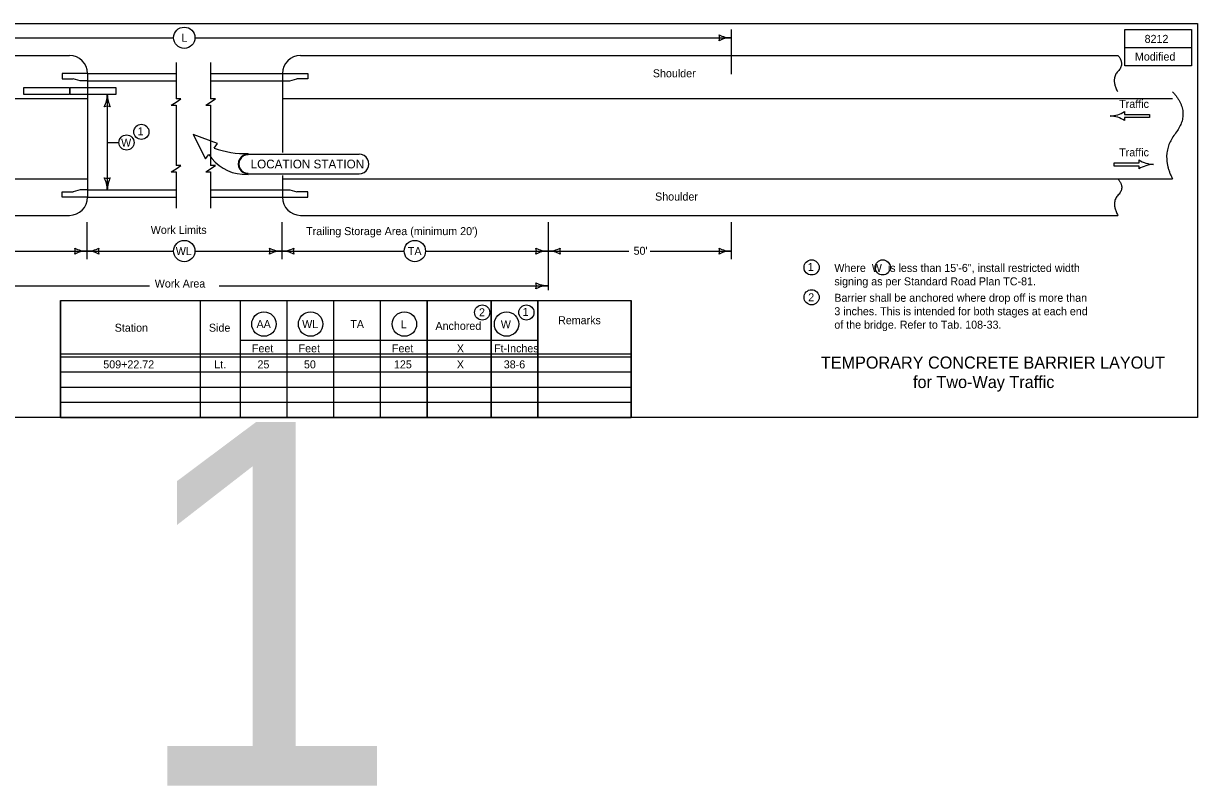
# Model space of a CAD drawing. Extents: x 6410 to 81668, y 3928 to 11667.
# Drawn here: x 11320 to 13257, y 10409 to 11667 of the extents above; entities that cross this region are included whole.
import ezdxf

# ---------------------------------------------------------------- set-up
doc = ezdxf.new("R2010")
doc.units = 0
doc.layers.add('dsnStdSection', color=7, linetype='Continuous')

msp = doc.modelspace()

# ---------------------------------------------------------------- linework, layer by layer
at = {"layer": 'dsnStdSection'}
for p, q in [((10152.2, 11666.6), (13257.2, 11666.6)), ((13257.2, 11666.6), (13257.2, 11016.6)), ((10635.1, 11643), (11568, 11643)), ((11603, 11643), (12487.8, 11643)), ((11615.6, 11643), (11746.2, 11643)), ((12487.8, 11656.8), (12487.8, 11583.2)), ((10267.5, 11614), (11396, 11614)), ((11777.4, 11614), (13125.8, 11614)), ((11426, 11584), (11384, 11584)), ((11384, 11584), (11384, 11575)), ((11426, 11584), (11572, 11584)), ((11426, 11584), (11426, 11380)), ((11572, 11602), (11572, 11542.1)), ((11629, 11602), (11629, 11542.1)), ((11629, 11584), (11747.4, 11584)), ((11747.4, 11584), (11789.4, 11584)), ((11747.4, 11584), (11747.4, 11453.9)), ((11789.4, 11584), (11789.4, 11575)), ((11384, 11575), (11402, 11575)), ((11414, 11572), (11402, 11575)), ((11426, 11572), (11414, 11572)), ((11426, 11572), (11572, 11572)), ((11629, 11572), (11747.4, 11572)), ((11747.4, 11572), (11759.4, 11572)), ((11759.4, 11572), (11771.4, 11575)), ((11789.4, 11575), (11771.4, 11575)), ((11458.5, 11549.2), (11458.5, 11392)), ((10179.2, 11542.9), (11426, 11542.9)), ((11564, 11532), (11572, 11537)), ((11564, 11532), (11572, 11532)), ((11572, 11537), (11580, 11542.1)), ((11580, 11542.1), (11572, 11542.1)), ((11572, 11532), (11572, 11482)), ((11621, 11532), (11637, 11542.1)), ((11621, 11532), (11629, 11532)), ((11637, 11542.1), (11629, 11542.1)), ((11629, 11532), (11629, 11482)), ((11747.4, 11542.9), (13216.1, 11542.9)), ((13113, 11513.9), (13113, 11513.9)), ((13136.9, 11521.4), (13136.9, 11516.2)), ((13136.9, 11516.2), (13178.1, 11516.2)), ((13178.1, 11511.7), (13136.9, 11511.7)), ((13136.9, 11511.7), (13136.9, 11506.4)), ((13178.1, 11516.2), (13178.1, 11511.7)), ((11458.5, 11470.1), (11477.8, 11470.1)), ((11572, 11482), (11572, 11432.1)), ((11600.3, 11483.4), (11620.4, 11443.4)), ((11640.5, 11468.4), (11600.3, 11483.4)), ((11629, 11482), (11629, 11432.1)), ((11634.6, 11461.1), (11640.5, 11468.4)), ((11620.4, 11443.4), (11626, 11450.4)), ((11690.8, 11450), (11690.8, 11451.8)), ((11690.8, 11450.9), (11873.9, 11450.9)), ((11572, 11427), (11580, 11432.1)), ((11580, 11432.1), (11572, 11432.1)), ((11621, 11422), (11637, 11432.1)), ((11637, 11432.1), (11629, 11432.1)), ((13160.5, 11436.3), (13119.2, 11436.3)), ((13119.2, 11436.3), (13119.2, 11431.8)), ((13119.2, 11431.8), (13160.5, 11431.8)), ((13160.5, 11441.5), (13160.5, 11436.3)), ((13160.5, 11431.8), (13160.5, 11426.5)), ((13184.4, 11434), (13184.4, 11434)), ((10183.9, 11410), (11426, 11410)), ((11564, 11422), (11572, 11427)), ((11564, 11422), (11572, 11422)), ((11572, 11422), (11572, 11362)), ((11621, 11422), (11629, 11422)), ((11629, 11422), (11629, 11362)), ((11681.2, 11417.9), (11690.8, 11417.5)), ((11690.8, 11417.5), (11690.8, 11419.3)), ((11690.8, 11418.4), (11873.9, 11418.4)), ((11747.4, 11415.8), (11747.4, 11380)), ((11747.4, 11410), (13216.1, 11410)), ((11414, 11392), (11402, 11389)), ((11426, 11392), (11414, 11392)), ((11426, 11392), (11572, 11392)), ((11629, 11392), (11747.4, 11392)), ((11747.4, 11392), (11759.4, 11392)), ((11759.4, 11392), (11771.4, 11389)), ((11384, 11389), (11402, 11389)), ((11384, 11380), (11384, 11389)), ((11426, 11380), (11384, 11380)), ((11426, 11380), (11572, 11380)), ((11629, 11380), (11747.4, 11380)), ((11747.4, 11380), (11789.4, 11380)), ((11789.4, 11389), (11771.4, 11389)), ((11789.4, 11380), (11789.4, 11389)), ((10267.5, 11350), (11396, 11350)), ((11424.8, 11338.8), (11424.8, 11277.5)), ((11746.2, 11338.8), (11746.2, 11277.5)), ((11777.4, 11350), (13125.8, 11350)), ((12185.7, 11338.8), (12185.7, 11226.4)), ((12487.8, 11338.8), (12487.8, 11277.5)), ((11198.7, 11291), (11424.8, 11291)), ((11424.8, 11291), (11568, 11291)), ((11603, 11291), (11746.2, 11291)), ((11615.6, 11291), (11746.2, 11291)), ((11746.2, 11291), (11948.3, 11291)), ((11983.5, 11291), (12185.7, 11291)), ((12185.7, 11291), (12319.1, 11291)), ((12354.4, 11291), (12487.8, 11291)), ((10937.3, 11233.9), (11528.1, 11233.9)), ((11643.3, 11233.9), (12185.7, 11233.9)), ((11644.7, 11233.9), (11746.2, 11233.9)), ((11381.4, 11209.6), (11381.4, 11016.6)), ((11381.4, 11209.6), (12323, 11209.6)), ((11381.4, 11016.6), (11381.4, 11209.6)), ((11381.4, 11209.6), (12323, 11209.6)), ((11612.4, 11016.6), (11612.4, 11209.6)), ((11678.4, 11016.6), (11678.4, 11209.6)), ((11755.4, 11016.6), (11755.4, 11209.6)), ((11832.4, 11016.6), (11832.4, 11209.6)), ((11909.4, 11016.6), (11909.4, 11209.6)), ((11986.4, 11016.6), (11986.4, 11209.6)), ((11986.4, 11209.6), (11986.4, 11016.6)), ((12092, 11016.6), (12092, 11209.6)), ((12092, 11209.6), (12092, 11016.6)), ((12169, 11016.6), (12169, 11209.6)), ((12169, 11209.6), (12169, 11016.6)), ((12323, 11016.6), (12323, 11209.6)), ((12323, 11209.6), (12323, 11016.6)), ((11678.4, 11143.8), (12169, 11143.8)), ((11381.4, 11121.6), (12323, 11121.6)), ((11381.4, 11116.6), (12323, 11116.6)), ((11381.4, 11091.6), (12323, 11091.6)), ((11381.4, 11066.6), (12323, 11066.6)), ((11381.4, 11041.6), (12323, 11041.6)), ((13257.2, 11016.6), (10152.2, 11016.6)), ((11381.4, 11016.3), (12323, 11016.3))]:
    msp.add_line(p, q, dxfattribs=at)
msp.add_lwpolyline([(13247.2, 11656.6), (13247.2, 11596.6), (13137.2, 11596.6), (13137.2, 11656.6), (13247.2, 11656.6), (13247.2, 11626.6), (13137.2, 11626.6)], dxfattribs=at)
for points in [[(11321, 11561.2), (11396, 11561.2), (11396, 11549.2), (11321, 11549.2)], [(11397.5, 11561.2), (11472.5, 11561.2), (11472.5, 11549.2), (11397.5, 11549.2)]]:
    msp.add_lwpolyline(points, close=True, dxfattribs=at)
for centre, radius in [((11585.5, 11643), 17.6), ((11514.7, 11487.7), 12.5), ((11490.3, 11470.1), 12.5), ((11585.5, 11291), 17.6), ((11965.9, 11291), 17.6), ((12620.5, 11264.1), 12.5), ((12737.8, 11264.1), 12.5), ((12620.5, 11214.8), 12.5), ((12077.1, 11189.8), 12.5), ((12149.9, 11189.8), 12.5), ((11716.9, 11170.6), 20.1), ((11793.9, 11170.6), 20.1), ((11948.7, 11170.6), 20.1), ((12117.2, 11170.6), 20.1)]:
    msp.add_circle(centre, radius, dxfattribs=at)
for centre, radius, start, end in [((12452.2, 11643), 16.4, 342.2666, 17.7333), ((12487.8, 11685.5), 42.5, 241.9275, 270), ((12487.8, 11600.5), 42.5, 90, 118.0725), ((11396, 11584), 30, 0, 90), ((11777.4, 11584), 30, 90, 180), ((11416, 11549.2), 42.5, 331.9275, 360), ((11501, 11549.2), 42.5, 180, 208.0725), ((11458.5, 11513.5), 16.4, 72.2666, 107.7334), ((13111, 11562.2), 48.4, 272.352, 302.382), ((13111, 11465.6), 48.4, 57.618, 87.648), ((13186.4, 11482.4), 48.4, 237.618, 267.648), ((13186.4, 11385.7), 48.4, 92.352, 122.382), ((11458.5, 11427.7), 16.4, 252.2666, 287.7333), ((11416, 11392), 42.5, 360, 28.0725), ((11501, 11392), 42.5, 151.9275, 180), ((11396, 11380), 30, 270, 360), ((11777.4, 11380), 30, 180, 270), ((11389.1, 11291), 16.4, 342.2666, 17.7333), ((11424.8, 11333.5), 42.5, 241.9275, 270), ((11424.8, 11333.5), 42.5, 270, 298.0725), ((11460.4, 11291), 16.4, 162.2666, 197.7334), ((11710.5, 11291), 16.4, 342.2666, 17.7333), ((11746.2, 11333.5), 42.5, 241.9275, 270), ((11746.2, 11333.5), 42.5, 270, 298.0725), ((11781.8, 11291), 16.4, 162.2666, 197.7334), ((12150, 11291), 16.4, 342.2666, 17.7333), ((12185.7, 11333.5), 42.5, 241.9275, 270), ((12185.7, 11333.5), 42.5, 270, 298.0725), ((12221.3, 11291), 16.4, 162.2666, 197.7334), ((12452.2, 11291), 16.4, 342.2666, 17.7333), ((12487.8, 11333.5), 42.5, 241.9275, 270), ((11424.8, 11248.5), 42.5, 90, 118.0725), ((11424.8, 11248.5), 42.5, 61.9275, 90), ((11746.2, 11248.5), 42.5, 90, 118.0725), ((11746.2, 11248.5), 42.5, 61.9275, 90), ((12185.7, 11248.5), 42.5, 90, 118.0725), ((12185.7, 11248.5), 42.5, 61.9275, 90), ((12487.8, 11248.5), 42.5, 90, 118.0725), ((12150, 11233.9), 16.4, 342.2666, 17.7333), ((12185.7, 11276.4), 42.5, 241.9275, 270), ((12185.7, 11191.4), 42.5, 90, 118.0725)]:
    msp.add_arc(centre, radius, start, end, dxfattribs=at)
for centre, major_axis, start_param, end_param in [((11685.8, 11488.2), (-70.8, 0), 0.565405, 1.506314), ((11687.9, 11607.9), (-156.9, 0), 1.224052, 1.588892), ((11690.8, 11434.7), (-16.3, 0), 4.712389, 7.853982), ((11690.8, 11434.7), (15.4, 0), 1.570796, 4.712389), ((11873.9, 11434.7), (16.3, 0), 4.712389, 7.853982)]:
    msp.add_ellipse(centre, major_axis=major_axis, ratio=0.995025, start_param=start_param, end_param=end_param, dxfattribs=at)
for points in [[(13125.8, 11614), (13137.6, 11599.9), (13114, 11574.9), (13125.3, 11554.1)], [(13216.1, 11554), (13247.6, 11519.6), (13194.2, 11451.6), (13216.1, 11410)], [(13126.2, 11410), (13138, 11395.9), (13114.4, 11370.9), (13125.8, 11350)]]:
    msp.add_open_spline(points, degree=2, dxfattribs=at)

# ---------------------------------------------------------------- texts
for s, height, p in [('L', 13.2, (11580.6, 11636.4)), ('8212', 13.2, (13169.9, 11634.6)), ('Modified', 13.2, (13153.9, 11605.4)), ('Shoulder', 13.2, (12358.6, 11577.8)), ('Traffic', 13.2, (13128, 11527.3)), ('1', 13.2, (11508.5, 11482)), ('W', 13.2, (11481.3, 11463.5)), ('Traffic', 13.2, (13128, 11447.4)), ('LOCATION STATION', 14.4, (11695, 11427.5)), ('Shoulder', 13.2, (12362.3, 11374.4)), ('Work Limits', 13.2, (11530.2, 11319.4)), ("Trailing Storage Area (minimum 20')", 13.2, (11786.6, 11317.4)), ('WL', 13.2, (11571.5, 11284.4)), ('TA', 13.2, (11954.4, 11284.4)), ("50'", 13.2, (12326.8, 11285)), ('1', 13.2, (12614.2, 11258.4)), ('Where  W  is less than 15\'-6", install restricted width', 13.2, (12658, 11256.7)), ('Work Area', 13.2, (11536.8, 11230.9)), ('signing as per Standard Road Plan TC-81.', 13.2, (12658, 11234.5)), ('2', 13.2, (12614.9, 11208.2)), ('Barrier shall be anchored where drop off is more than ', 13.2, (12658, 11207.4)), ('2', 13.2, (12071.8, 11183.5)), ('1', 13.2, (12143.6, 11184.1)), ('3 inches. This is intended for both stages at each end ', 13.2, (12658, 11185.2)), ('AA', 13.2, (11704.7, 11164)), ('WL', 13.2, (11780, 11164)), ('TA', 13.2, (11859.4, 11164)), ('L', 13.2, (11942.9, 11163.6)), ('W', 13.2, (12107.7, 11163.6)), ('Remarks', 13.2, (12202.2, 11170.4)), ('of the bridge. Refer to Tab. 108-33.', 13.2, (12658, 11163)), ('Station', 13.2, (11470.7, 11158)), ('Side', 13.2, (11626.2, 11158)), ('Anchored', 13.2, (11999.9, 11161)), ('Ft-Inches', 13.2, (12096.6, 11124)), ('Feet', 13.2, (11697.1, 11124)), ('Feet', 13.2, (11774.1, 11124)), ('Feet', 13.2, (11928.1, 11124)), ('X', 13.2, (12035.2, 11124)), ('509+22.72', 13.2, (11451.9, 11097.5)), ('Lt.', 13.2, (11635, 11097.5)), ('25', 13.2, (11706.3, 11097.5)), ('50', 13.2, (11783, 11097.5)), ('125', 13.2, (11931.4, 11097.5)), ('X', 13.2, (12035.2, 11097.5)), ('38-6', 13.2, (12112.6, 11097.5)), ('TEMPORARY CONCRETE BARRIER LAYOUT', 20, (12635.7, 11097.1)), ('for Two-Way Traffic', 20, (12787.8, 11065.1)), ('1', 600, (11496.6, 10409.2))]:
    msp.add_text(s, height=height, dxfattribs=at).set_placement(p)

doc.saveas('drawing.dxf')
